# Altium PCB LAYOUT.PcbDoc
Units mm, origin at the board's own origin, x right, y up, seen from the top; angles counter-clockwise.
Board outline 137.2 x 25.65 mm, 2 copper layers (Top Layer, Bottom Layer), stack 0.871 mm thick; 14 components, 30 nets, 82 pads, 15 vias.
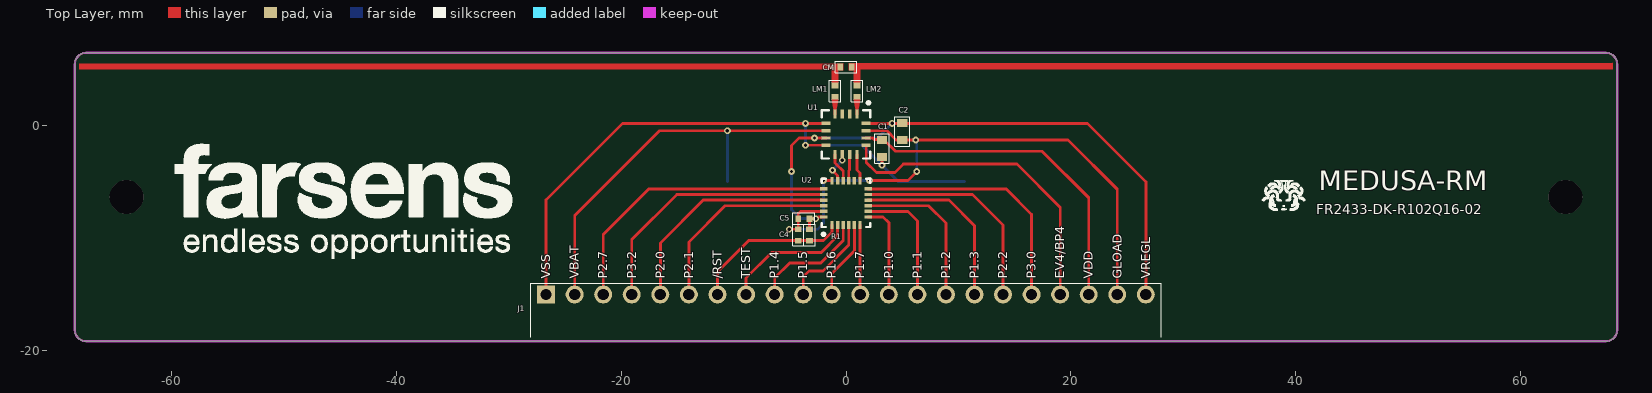
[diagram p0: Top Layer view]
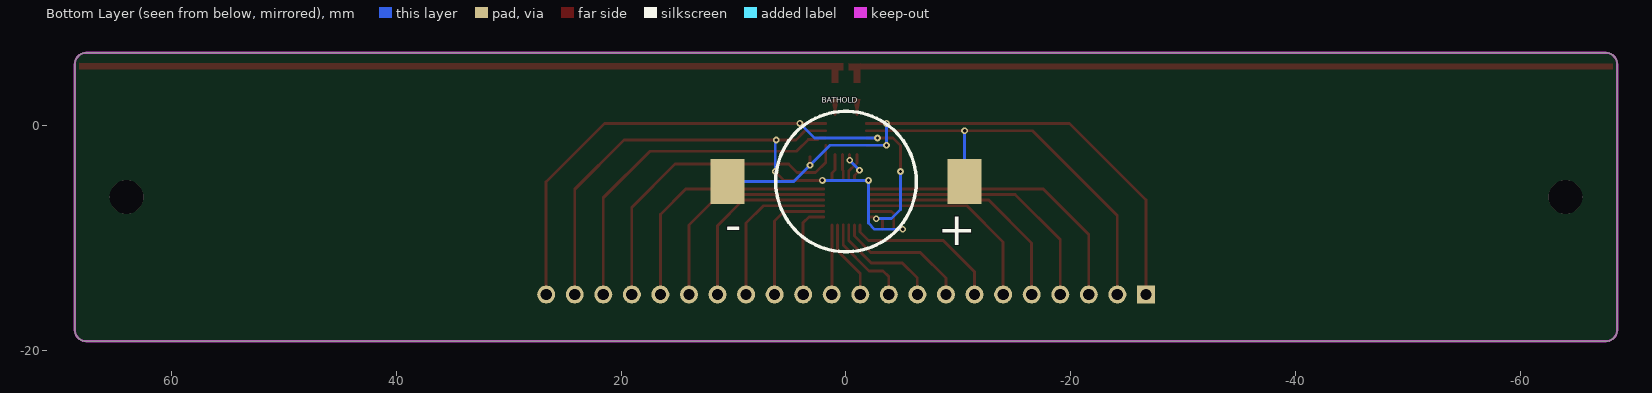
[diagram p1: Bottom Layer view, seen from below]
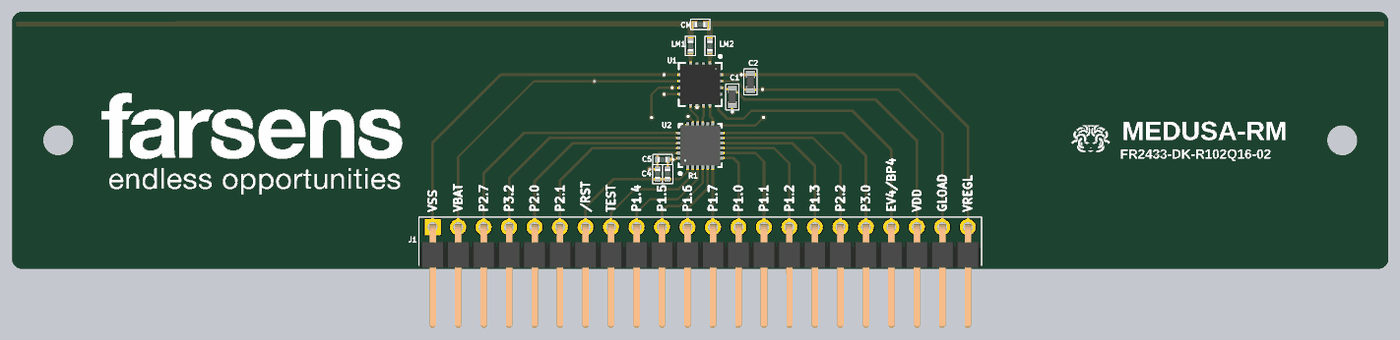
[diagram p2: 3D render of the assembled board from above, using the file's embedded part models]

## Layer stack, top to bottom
Top Solder: solder mask 0.0102, Solder Resist, Dk 3.5
Top Layer: signal copper 0.0356
Dielectric1: core 0.8, FR-4, Dk 4.8
Bottom Layer: signal copper 0.0356
Bottom Solder: solder mask 0.0102, Solder Resist, Dk 3.5

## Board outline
-67.6,-19.2 cw(c-67.6,-18.2) -68.6,-18.2 -68.6,5.45 cw(c-67.6,5.45) -67.6,6.45 67.6,6.45 cw(c67.6,5.45) 68.6,5.45 68.6,-18.2 cw(c67.6,-18.2) 67.6,-19.2

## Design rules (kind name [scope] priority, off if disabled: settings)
Clearance [All] p1: gap=0.2 ignorepadtopadclearanceinfootprint=FALSE except(0: Arc-Hole Track-Hole SMDPad-Hole THPad-Hole Via-Hole Fill-Hole Poly-Hole Region-Hole Text-Hole)
ComponentClearance [All] p1: gap=0.2 collisioncheckmode=3 verticalgap=0.2 showdistances=FALSE
HoleSize [All] p1: absolutevalues=TRUE maxlimit=3 minlimit=0.025 maxpercent=80.000 minpercent=20.000
HoleToHoleClearance [All] p1: gap=0.2 allowstackedmicrovias=TRUE
MinimumSolderMaskSliver [All] p1: minsoldermaskwidth=0.1
PlaneClearance [All] p1: clearance=1
PlaneConnect [All] p1: planeconnectstyle=Relief reliefexpansion=0.5 reliefentries=4 reliefconductorwidth=0.25 reliefairgap=0.5
PolygonConnect [All] p1: connectstyle=Direct reliefconductorwidth=0.5 reliefentries=4 polygonreliefangle="90 Angle" airgapwidth=0.254
RoomDefinition SCHEMATIC [InComponentClass('SCHEMATIC')] p1: confinementstyle=ConfineIn formatcopy=TRUE lockcomponents=FALSE outline -70.1,-28.5 72.95,-28.5 72.95,8 -70.1,8
RoutingCorners [All] p1: cornerstyle=45-Degree minsetback=2.5 maxsetback=2.5
RoutingVias [All] p1: holewidth=0.711 width=1.27 viastyle="Through Hole" minholewidth=0.2 minwidth=0.4 maxholewidth=3 maxwidth=5
SilkToSilkClearance [All] p1: silktosilkclearance=0.1
SilkToSolderMaskClearance SilkscreenOverComponentPads [IsPad] p1: minsilkscreentomaskgap=0.05 clearancetoexposedcopper=TRUE
SolderMaskExpansion [All] p1: expansion=0.1
Width [All] p1: maxlimit=3 minlimit=0.1 preferedwidth=0.25 bottomlayer_minwidth=0.2 minimp=50.000000 maximp=50.000000 favimp=50.000000
21 further rules are at their usual default settings.

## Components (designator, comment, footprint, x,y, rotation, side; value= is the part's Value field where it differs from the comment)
BATHOLD "SMTU1225-LF" SMTU1225-LF 0,-5 r0 bottom
C1 "Capacitor" "LCR 0603 (1608)" 3.2,-2.05 r270 top
C2 "Capacitor" "LCR 0603 (1608)" 5,-0.55 r270 top
C4 "Capacitor" "LCR 0402 (1005)" -4.25,-9.75 r90 top
C5 "Capacitor" "LCR 0402 (1005)" -3.75,-8.3 r180 top
CM "Capacitor" "LCR 0402 (1005)" 0,5.2 r0 top
J1 "Header No.22_R/A" 61302211021 0,-15.05 r0 top
LM1 "Inductor" "LCR 0402 (1005)" -0.975,3.05 r90 top
LM2 "Inductor" "LCR 0402 (1005)" 0.975,3.05 r90 top
MEDUSA-RM "BOARD_NAME" BOARD_NAME 43.05,-10.3 r90 top (schematic designator MEDUSA-R)
R1 "Resistor" "LCR 0402 (1005)" -3.25,-9.75 r90 top
U1 "R102" R102 0,-0.8 r270 top
U2 "MSP430FR2433IRGET" MSP430FR2433IRGET 0,-6.9 r90 top
? "Comment" "LOGO NEW MEDIUM" -45.2,-6.4 r0 top

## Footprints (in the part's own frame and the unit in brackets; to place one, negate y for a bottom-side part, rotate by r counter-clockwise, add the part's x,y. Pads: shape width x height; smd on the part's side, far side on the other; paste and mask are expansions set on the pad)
61302211021 [mm] "Header 22-Pin, Pitch 2.54mm, Right Angle"
  rect 1.6x1.6 hole 1: 1(-26.68,0)
  round 1.6 hole 1: 2(-24.14,0) 3(-21.6,0) 4(-19.06,0) 5(-16.52,0) 6(-13.98,0) 7(-11.43,0) 8(-8.89,0) 9(-6.35,0) 10(-3.81,0) 11(-1.27,0) 12(1.27,0) 13(3.81,0) 14(6.35,0) 15(8.89,0) 16(11.43,0) 17(13.97,0) 18(16.51,0) 19(19.05,0) 20(21.59,0) 21(24.13,0) 22(26.67,0)
  silkscreen extent -28.05,-3.8 28.04,1, body extent -27.94,-10.05 27.94,0.31, height 2.57
BOARD_NAME [mm] "BOARD_NAME"
"LCR 0402 (1005)" [mm] "CASE 0402, Body 1mm x 0.5mm"
  rect 0.5x0.6 smd: 1(-0.5,0) 2(0.5,0)
  silkscreen extent -0.97,-0.51 0.97,0.51, body extent -0.5,-0.25 0.5,0.25, height 0.35
"LCR 0603 (1608)" [mm] "CASE 0603, Body 1.6mm x 0.8mm"
  rect 0.7x0.9 smd: 1(-0.75,0) 2(0.75,0)
  silkscreen extent -1.3,-0.65 1.3,0.65, body extent -0.76,-0.38 0.76,0.38, height 0.75
"LOGO NEW MEDIUM" [mm] "LOGO"
  silkscreen extent -14.5,-5.4 15.5,4.76
MSP430FR2433IRGET [mm] "QFN, 24-Leads, Body 4,00x4,00mm, Pitch 0,50mm,"
  rect 0.7x0.3 smd mask+0.1: 1(-1.975,1.25) 2(-1.975,0.75) 3(-1.975,0.25) 4(-1.975,-0.25) 5(-1.975,-0.75) 6(-1.975,-1.25) 13(1.975,-1.25) 14(1.975,-0.75) 15(1.975,-0.25) 16(1.975,0.25) 17(1.975,0.75) 18(1.975,1.25)
  rect 0.3x0.7 smd mask+0.1: 7(-1.25,-1.975) 8(-0.75,-1.975) 9(-0.25,-1.975) 10(0.25,-1.975) 11(0.75,-1.975) 12(1.25,-1.975) 19(1.25,1.975) 20(0.75,1.975) 21(0.25,1.975) 22(-0.25,1.975) 23(-0.75,1.975) 24(-1.25,1.975)
  silkscreen extent -2.92,-2.15 2.15,2.15, body extent -2,-2 2,2, height 0.9
R102 [mm] "QFN, 16-Leads, Body 4,00x4,00mm, Pitch 0,65mm,"
  rect 0.8x0.3 smd: 1(-1.8,0.975) 2(-1.8,0.325) 3(-1.8,-0.325) 4(-1.8,-0.975) 9(1.8,-0.975) 10(1.8,-0.325) 11(1.8,0.325) 12(1.8,0.975)
  rect 0.3x0.8 smd: 5(-0.975,-1.8) 6(-0.325,-1.8) 7(0.325,-1.8) 8(0.975,-1.8) 13(0.975,1.8) 14(0.325,1.8) 15(-0.325,1.8) 16(-0.975,1.8)
  silkscreen extent -2.92,-2.15 2.15,2.15, body extent -2,-2 2,2, height 0.92
SMTU1225-LF [mm] "Battery holder, CR1225 coin cell"
  rect 3x4 smd: 1(-10.55,0) 2(10.55,0)
  silkscreen extent -6.25,-6.25 6.25,6.25, body extent -11.78,-6.12 11.76,6.2, height 5.03

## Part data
BATHOLD: "Battery holder", 03 Value=CR1225, 06 Manufacturer=RENATA
C1: 03 Value=22uF, 06 Manufacturer=AVX, 07 Manufacturer Reference=06036D226MAT2A
C2: 03 Value=1uF, 06 Manufacturer=MURATA, 07 Manufacturer Reference=GRM188R71C105KA12D
C4: 03 Value=1nF, 06 Manufacturer=MURATA, 07 Manufacturer Reference=GRM155R71H102KA01D
C5: 03 Value=100nF, 06 Manufacturer=MURATA, 07 Manufacturer Reference=GRM155R71C104KA88D
CM: 03 Value=1pF, 06 Manufacturer="Johanson Dielectrics", 07 Manufacturer Reference=500R07S1R0BV4T
J1: "1-Row, 22-Pin, Pitch 2.54mm, Right Angle", 06 Manufacturer=MOLEX, 07 Manufacturer Reference=22-28-6220
LM1 LM2: 03 Value=36nH, 06 Manufacturer=MURATA, 07 Manufacturer Reference=LQW15AN36NG00D
MEDUSA-RM: "LOGO FARSENS", 06 Manufacturer=Farsens
R1: 03 Value=10K, 06 Manufacturer=PANASONIC, 07 Manufacturer Reference=ERJ-2RKF1002X
U1: "RFID TAG", 06 Manufacturer=FARSENS, 07 Manufacturer Reference=R102Q16
U2: "Mixed-Signal Microcontroller", 06 Manufacturer="Silicon Labs"

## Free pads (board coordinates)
  round 3 hole 3 unplated mask+0: ""(-64,-6.375) ""(64,-6.375)

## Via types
v1: diameter 0.6, hole 0.3, Top Layer to Bottom Layer, tented both sides, 15 vias

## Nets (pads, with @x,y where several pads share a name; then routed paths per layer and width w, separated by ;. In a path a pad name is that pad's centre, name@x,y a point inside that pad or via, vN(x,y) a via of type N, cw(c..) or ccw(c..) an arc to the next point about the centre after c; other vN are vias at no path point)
/RST: C4.1 J1.7 R1.1 U2.1 | length 14.3
  Top Layer w0.25: J1.7@-11.425,-15.05 -11.425,-13.025 -8.65,-10.25 C4.1 R1.1 -2,-10.25 -1.25,-9.5 U2.1
GLOAD: C2.2 C4.2 C5.2 J1.21 U1.15 U2.18 U2.23 | length 57.7
  Top Layer w0.25: v1(-5.05,-9.25) C4.2 C5.2 -4.25,-7.85 -4.05,-7.65 U2.23 ; v1(-2.002,-4.898) U2.18@-1.277,-4.898 ; U1.15 3.635,-0.475 4.46,-1.3 C2.2 v1(6.2,-1.3) 19.75,-1.3 24.135,-5.685 J1.21@24.135,-15.05 ; v1(2.1,-4.9) 5.5,-4.9 v1(6.3,-4.1)
  Bottom Layer w0.25: v1(-5.05,-9.25) -2.55,-9.25 -2.002,-8.702 v1(-2.002,-4.898) -2,-4.9 v1(2.1,-4.9) ; v1(6.2,-1.3) 6.3,-1.4 v1(6.3,-4.1)
IO0/MISO: U1.9 U2.16 | length 2.6
  Top Layer w0.25: U1.9 -0.975,-3.341 -0.891,-3.425 -0.25,-4.066 U2.16
IO1/MOSI: U1.10 U2.17 | length 2.9
  Top Layer w0.25: v1@-1.209,-3.991 -0.75,-4.45 U2.17 ; v1(-0.325,-3.107) U1.10
  Bottom Layer w0.25: v1@-1.209,-3.991 v1(-0.325,-3.107)
  other v1: -1.2,-4
IO2/SCK: U1.11 U2.15 | length 2.4
  Top Layer w0.25: U2.15 0.25,-4.05 0.325,-3.975 U1.11
IO3/CS: U1.12 U2.13 | length 2.4
  Top Layer w0.25: U1.12 0.975,-3.975 1.25,-4.25 U2.13
IO4: J1.19 U1.13 | length 28.8
  Top Layer w0.25: U1.13 1.8,-3.3 2.7,-4.2 4.35,-4.2 5.1,-3.45 15.2,-3.45 19.055,-7.305 J1.19@19.055,-15.05
NetCM_1: CM.1 LM1.2
NetCM_2: CM.2 LM2.2
P1.0: J1.13 U2.7 | length 8.4
  Top Layer w0.25: U2.7 3.3,-8.15 3.815,-8.665 J1.13@3.815,-15.05
P1.1: J1.14 U2.8 | length 11.3
  Top Layer w0.25: U2.8 5.5,-7.65 6.355,-8.505 J1.14@6.355,-15.05
P1.2: J1.15 U2.9 | length 13.9
  Top Layer w0.25: U2.9 7.35,-7.15 8.895,-8.695 J1.15@8.895,-15.05
P1.3: J1.16 U2.10 | length 16.5
  Top Layer w0.254: U2.10 9.15,-6.65 11.435,-8.935 J1.16@11.435,-15.05
P1.4: J1.9 U2.3 | length 10.3
  Top Layer w0.25: J1.9@-6.345,-15.05 -6.345,-13.595 -5,-12.25 -2.25,-12.25 -0.25,-10.25 U2.3
P1.5: J1.10 U2.4 | length 8.6
  Top Layer w0.25: J1.10@-3.805,-15.05 -3.805,-13.455 -3.3,-12.95 -2.05,-12.95 0.25,-10.65 U2.4
P1.6: J1.11 U2.5 | length 7
  Top Layer w0.25: J1.11@-1.265,-15.05 -1.265,-13.165 0.75,-11.15 U2.5
P1.7: J1.12 U2.6 | length 6.2
  Top Layer w0.25: U2.6 1.25,-15.025 J1.12@1.275,-15.05
P2.0: J1.5 U2.21 | length 20.7
  Top Layer w0.25: J1.5@-16.515,-15.05 -16.515,-10.465 -12.7,-6.65 U2.21
P2.1: J1.6 U2.22 | length 18
  Top Layer w0.25: J1.6@-13.975,-15.05 -13.975,-10.375 -10.75,-7.15 U2.22
P2.2: J1.17 U2.11 | length 19.3
  Top Layer w0.25: U2.11 11.25,-6.15 13.975,-8.875 J1.17@13.975,-15.05
P2.7: J1.3 U2.19 | length 26.7
  Top Layer w0.25: J1.3@-21.595,-15.05 -21.595,-9.695 -17.55,-5.65 U2.19
P3.0: J1.18 U2.12 | length 22.6
  Top Layer w0.25: U2.12 14.25,-5.65 16.515,-7.915 J1.18@16.515,-15.05
P3.2: J1.4 U2.20 | length 23.6
  Top Layer w0.25: J1.4@-19.055,-15.05 -19.055,-10.155 -15.05,-6.15 U2.20
RFN: LM1.1 U1.4 | length 1.3
  Top Layer w0.3: U1.4 -0.975,2.3
RFP: LM2.1 U1.1 | length 0.8
  Top Layer w0.3: U1.1 0.975,1.8
TEST: J1.8 U2.2 | length 12.1
  Top Layer w0.254: J1.8@-8.885,-15.05 -8.885,-13.585 -6.6,-11.3 -2.2,-11.3 -0.75,-9.85 U2.2
VBAT: BATHOLD.1 J1.2 U1.6 | length 37
  Top Layer w0.25: J1.2@-24.135,-15.05 -24.135,-8.035 -16.575,-0.475 v1(-10.55,-0.475) U1.6
  Bottom Layer w0.25: BATHOLD.1 v1(-10.55,-0.475)
VDD: C1.1 J1.20 U1.14 | length 30.6
  Top Layer w0.25: U1.14 2.375,-1.125 2.5,-1.25 3.35,-1.25 4.4,-2.3 17.45,-2.3 21.595,-6.445 J1.20@21.595,-15.05
VREGL: C2.1 C5.1 J1.22 R1.2 U1.7 U1.16 U2.24 | length 58.3
  Top Layer w0.25: v1(-4.85,-4.1) -4.85,-1.8 -4.175,-1.125 v1(-2.8,-1.125) U1.7 ; R1.2 C5.1 v1(-2.7,-8.3) -2.65,-8.3 -2.5,-8.15 U2.24 ; U1.16 v1(4.1,0.175) 21.475,0.175 26.675,-5.025 J1.22@26.675,-15.05
  Bottom Layer w0.25: v1(-4.85,-4.1) -4.85,-7.5 -4.05,-8.3 v1(-2.7,-8.3) ; v1(-2.8,-1.125) 2.8,-1.125 v1(4.1,0.175)
VSS: BATHOLD.2 C1.2 J1.1 U1.5 U1.8 | length 56.1
  Top Layer w0.25: J1.1@-26.675,-15.05 -26.675,-6.625 -19.875,0.175 v1(-3.6,0.175) U1.5 ; v1(-3.6,-1.775) U1.8 ; v1(3.2,-3.55) C1.2
  Bottom Layer w0.25: v1(-3.6,0.175) v1(-3.6,-1.775) 1.425,-1.775 v1(3.2,-3.55) 4.65,-5 BATHOLD.2
pads on no net: U1.2 U1.3 U2.14

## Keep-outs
Keep-Out Layer:
  the board outline again, w0.2

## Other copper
Top Layer:
  pour cut-out: -2.15,0.6 2.15,0.6 2.15,1.4 -2.15,1.4
  region net NetCM_2: 0.675,3.8 0.675,4.9 0.25,4.9 0.25,5.5 1.275,5.503 1.275,3.8
  region net NetCM_1: -68.2,5 -0.25,4.996 -0.25,5.504 -68.2,5.5
  region net NetCM_2: 0.25,4.996 68.2,5 68.2,5.55 0.25,5.503
  region net NetCM_1: -1.275,3.8 -1.275,5.503 -0.25,5.5 -0.25,4.9 -0.675,4.9 -0.675,3.8
  region net RFN: -1.275,2.3 -1.125,1.5 -0.825,1.5 -0.675,2.3
  region net RFP: 0.675,2.3 0.825,1.5 1.125,1.5 1.275,2.3

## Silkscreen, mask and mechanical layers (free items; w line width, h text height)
Top Overlay:
  drawing of 557 lines, arcs and shapes, not listed
  text "VSS" at -26.3,-13.65 h0.8 r90
  text "VBAT" at -23.76,-13.65 h0.8 r90
  text "P2.7" at -21.219,-13.65 h0.8 r90
  text "P3.2" at -18.679,-13.65 h0.8 r90
  text "P2.0" at -16.138,-13.65 h0.8 r90
  text "P2.1" at -13.598,-13.65 h0.8 r90
  text "/RST" at -11.057,-13.65 h0.8 r90
  text "TEST" at -8.517,-13.65 h0.8 r90
  text "P1.4" at -5.976,-13.65 h0.8 r90
  text "P1.5" at -3.436,-13.65 h0.8 r90
  text "P1.6" at -0.895,-13.65 h0.8 r90
  text "P1.7" at 1.645,-13.65 h0.8 r90
  text "P1.0" at 4.186,-13.65 h0.8 r90
  text "P1.1" at 6.726,-13.65 h0.8 r90
  text "P1.2" at 9.267,-13.65 h0.8 r90
  text "P1.3" at 11.807,-13.65 h0.8 r90
  text "P2.2" at 14.348,-13.65 h0.8 r90
  text "P3.0" at 16.888,-13.65 h0.8 r90
  text "EV4/BP4" at 19.429,-13.65 h0.8 r90
  text "VDD" at 21.969,-13.65 h0.8 r90
  text "GLOAD" at 24.509,-13.65 h0.8 r90
  text "VREGL" at 27.05,-13.65 h0.8 r90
